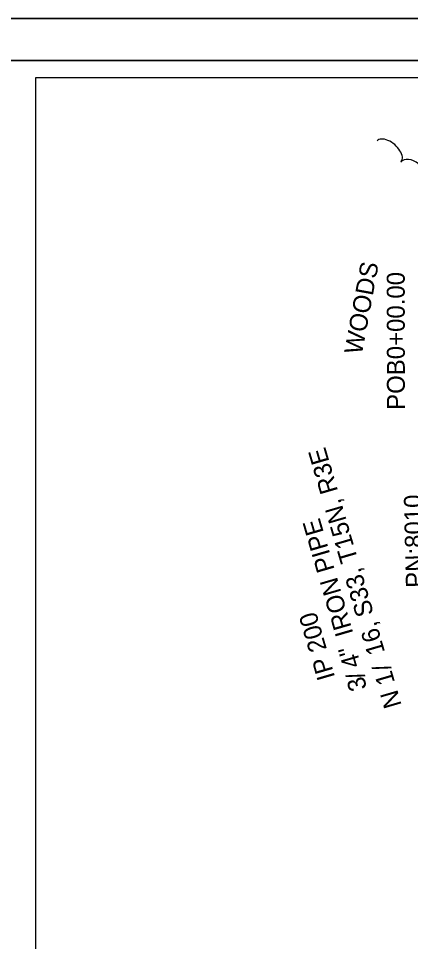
# Model space of a CAD drawing. Extents: x 1671357 to 13005564, y 567358 to 14261451.
# Drawn here: x 12758419.18 to 12758432.3, y 14259861.85 to 14259892.76 of the extents above; entities that cross this region are included whole.
import ezdxf

# ---------------------------------------------------------------- set-up
doc = ezdxf.new("R2010")
doc.units = 0
for name, color, linetype in [('Default', 7, 'Continuous'), ('R_Horz Alg Annot', 7, 'Continuous'), ('R_No Plot', 7, 'Continuous'), ('R_Survey Control', 7, 'Continuous'), ('S_TREE', 7, 'Continuous')]:
    doc.layers.add(name, color=color, linetype=linetype)

msp = doc.modelspace()

# ---------------------------------------------------------------- linework, layer by layer
at = {"layer": 'Default'}
for p, q in [((12758411.955, 14259892.757), (12758499.964, 14259892.757)), ((12758499.964, 14259892.757), (12758411.955, 14259892.757)), ((12758499.936, 14259891.351), (12758416.928, 14259891.351)), ((12758419.761, 14259890.781), (12758498.813, 14259890.781)), ((12758419.761, 14259839.411), (12758419.761, 14259890.781))]:
    msp.add_line(p, q, dxfattribs=at)
at = {"layer": 'R_No Plot'}
msp.add_lwpolyline([(12758416.928, 14259891.351), (12758499.936, 14259891.351), (12758499.936, 14259838.271), (12758416.928, 14259838.271)], close=True, dxfattribs=at)
at = {"layer": 'S_TREE'}
for centre, major_axis, ratio, start_param, end_param in [((12758431.583, 14259888.31), (-0.404, 0.345), 0.543829, 3.144573, 6.286166), ((12758432.345, 14259887.625), (-0.374, 0.321), 0.689272, 3.146662, 6.288254)]:
    msp.add_ellipse(centre, major_axis=major_axis, ratio=ratio, start_param=start_param, end_param=end_param, dxfattribs=at)

# ---------------------------------------------------------------- texts
at = {"layer": 'Default'}
for s, height, rotation, p in [('WOODS', 0.6001, 79.4668, (12758430.668, 14259881.477)), ('16, S33, T15N, R3E', 0.60006, 106.269, (12758431.452, 14259871.537)), ('IRON PIPE', 0.6001, 106.269, (12758430.39, 14259872.162)), ('IP 200', 0.6001, 106.269, (12758429.779, 14259870.697)), ('4"', 0.6001, 106.269, (12758430.645, 14259871.095)), ('/', 0.6, 106.269, (12758431.66, 14259870.991)), ('N 1', 0.6001, 106.269, (12758432.009, 14259869.759)), ('/', 0.6, 106.269, (12758430.783, 14259870.724)), ('3', 0.6, 106.269, (12758430.85, 14259870.332))]:
    msp.add_text(s, height=height, rotation=rotation, dxfattribs=at).set_placement(p)
at = {"layer": 'R_Horz Alg Annot'}
msp.add_text('POB0+00.00', height=0.6001, rotation=90.079, dxfattribs=at).set_placement((12758432.111, 14259879.65))
at = {"layer": 'R_Survey Control'}
msp.add_text('PN:8010', height=0.6001, rotation=91.3353, dxfattribs=at).set_placement((12758432.746, 14259873.698))

doc.saveas('drawing.dxf')
